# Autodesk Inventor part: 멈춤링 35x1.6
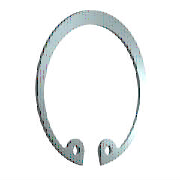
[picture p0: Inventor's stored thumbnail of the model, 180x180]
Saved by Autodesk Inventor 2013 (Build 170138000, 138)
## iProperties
IsCustomPart: 1
Created: 2015-09
Part Number: 멈춤링 35x1.6
Material: 강철, 연강
Description: 리테이닝 링(C형)
Document SubType Name: Modeling
Standard: KS B 1336
Designer: mduedu
Standards Organization: KS
Language: ko-KR
Size Designation: 35x1.6
Categories: <MemberInstance><Categories><Category DisplayName="샤프트 부품" InternalName="7f7aeb1f-a693-4053-b835-cee3144e0d98" Mnemonic="SHFT"><Category DisplayName="써클립" Inter
Density: 7.86 g/cm^3
Mass: 3.5371 g
Surface Area: 9.09651 cm^2
Volume: 0.450013 cm^3
Author: mduedu
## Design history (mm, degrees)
sketch "스케치1"
  geometry: L1 (0, 15.113)-(0, -73.177) reference; L2 (-45.5, 0)-(45.5, 0) reference; L3 (-4.964, 1)-(1.502, 1); L4 (0, -2.5)-(-5.307, -2.5); L5 (0, -17.5)-(-8.583, -33.888); L6 (-8.583, -33.888)-(-21.772, -26.981); L7 (-7.377, -31.585)-(-17.631, -26.214); L8 (-5.162, -32.745)-(-6.29, -34.898); L9 (5.162, -32.745)-(6.29, -34.898); C1 r 1.25 at (-7.377, -31.585); C2 r 1.25 at (7.377, -31.585); A1 r 15.875 centre (0, -18.375) between (11.82, -28.972) and (-11.82, -28.972); A2 r 18.5 centre (0, -17.5) between (6.29, -34.898) and (-6.29, -34.898); A3 r 2.5 centre (-7.377, -31.585) between (-5.162, -32.745) and (-8.668, -29.444); A4 r 2.5 centre (-9.959, -27.303) between (-11.82, -28.972) and (-8.668, -29.444); A5 r 2.5 centre (9.959, -27.303) between (8.668, -29.444) and (11.82, -28.972); A6 r 2.5 centre (7.377, -31.585) between (8.668, -29.444) and (5.162, -32.745); 3 further points
  constraints: 15 point on circle, 14 end point, 9 symmetric about line, 8 centre point, 6 tangent, 4 coincident, 4 point on line, 3 perpendicular, 1 parallel, 4 other
  dimensions: "d8" = 0.875 distance of A1.centre L5.start (= 0.25 x SRB1); "d38" = 3.5 distance between parallel lines of L4 L3 (= SRB1); "d39" = 17.5 distance from line of L5.start L2 (= 0.5 x WD); "d43" = 18.5 radius of A2 (= 0.5 x ND); "d45" = 2.6 distance between parallel lines of L7 L6 (= 0.5 x SRB2); "d46" = 2.5 radius of A4 (= SD5); "d47" = 6.29 distance from line of L1 L8.end (= 0.17 x ND); "d48" = 2.5 diameter of C1 (= SD5); "d49" = 2.5 radius of A3 (= SD5)
extrude "본체" new body sketch "스케치1" distance "d2" = 1.6 (= SD); taper "d3" = 0 deg
workaxis "Work Axis1"
workaxis "Work Axis2"
workplane "Work Plane1"
body "Solid1"
other parameters: "WD" = 35 [user parameter; used in 3 equation terms], "SD" = 1.6 [user parameter; used in 1 equation term], "SRB1" = 3.5 [user parameter; used in 2 equation terms], "ND" = 37 [user parameter; used in 2 equation terms], "SRB2" = 5.2 [user parameter; used in 1 equation term], "SD5" = 2.5 [user parameter; used in 3 equation terms], "d50" = 0, "d51" = 0, "d52" = 0, "d53" = 0, "WDMIN" = 34 [user parameter], "SD6" = 37.8 [user parameter], "WDMAX" = 35 (= WD) [user parameter], "NND" = 35 (= WD) [user parameter]
